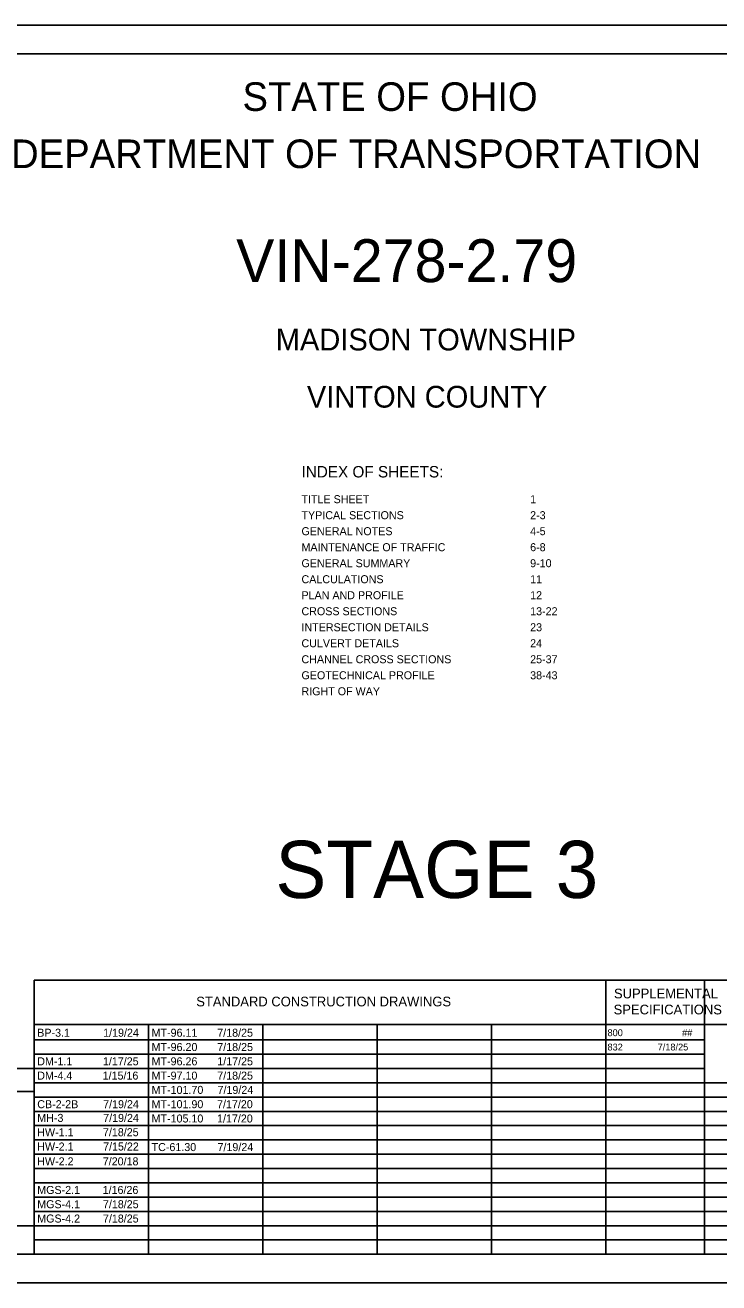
# Model space of a CAD drawing. Extents: x 0 to 34, y 0 to 22.
# Drawn here: x 9.99 to 22.13, y 0 to 22 of the extents above; entities that cross this region are included whole.
import ezdxf

# ---------------------------------------------------------------- set-up
doc = ezdxf.new("R2010")
doc.units = 0
for name, color, linetype in [('SH_Border', 7, 'Continuous'), ('SH_Cut_Line', 7, 'Continuous'), ('SH_Data', 7, 'Continuous'), ('SH_Text', 7, 'Continuous')]:
    doc.layers.add(name, color=color, linetype=linetype)

msp = doc.modelspace()

# ---------------------------------------------------------------- linework, layer by layer
at = {"layer": 'SH_Border'}
msp.add_lwpolyline([(1.5, 21.5), (33.5, 21.5), (33.5, 0.5), (1.5, 0.5)], close=True, dxfattribs=at)
at = {"layer": 'SH_Cut_Line'}
msp.add_lwpolyline([(0, 0), (34, 0), (34, 22), (0, 22)], close=True, dxfattribs=at)
at = {"layer": 'SH_Data'}
for p, q in [((10.15, 5.292), (23.6, 5.292)), ((10.15, 0.5), (10.15, 5.292)), ((20.15, 0.5), (20.15, 5.292)), ((21.875, 0.5), (21.875, 5.292)), ((10.15, 4.521), (23.6, 4.521)), ((12.15, 0.5), (12.15, 4.521)), ((14.15, 0.5), (14.15, 4.521)), ((16.15, 0.5), (16.15, 4.521)), ((18.15, 0.5), (18.15, 4.521)), ((10.15, 4.25), (21.875, 4.25)), ((10.15, 4), (21.875, 4)), ((10.15, 3.75), (7.35, 3.75)), ((10.15, 0.5), (10.15, 3.75)), ((10.15, 3.75), (21.875, 3.75)), ((10.15, 3.35), (7.35, 3.35)), ((10.15, 3.5), (23.6, 3.5)), ((10.15, 3.25), (23.6, 3.25)), ((10.15, 3), (23.6, 3)), ((10.15, 2.75), (23.6, 2.75)), ((10.15, 2.5), (23.6, 2.5)), ((10.15, 2.25), (23.6, 2.25)), ((10.15, 2), (23.6, 2)), ((10.15, 1.75), (23.6, 1.75)), ((10.15, 1.5), (23.6, 1.5)), ((10.15, 1.25), (23.6, 1.25)), ((10.15, 1), (23.6, 1)), ((10.15, 0.75), (23.6, 0.75)), ((10.15, 0.5), (7.35, 0.5))]:
    msp.add_line(p, q, dxfattribs=at)
msp.add_lwpolyline([(10.15, 0.5), (10.15, 1), (7.35, 1), (7.35, 0.5)], close=True, dxfattribs=at)

# ---------------------------------------------------------------- texts
at = {"layer": 'SH_Text'}
for s, height, p in [('STATE OF OHIO', 0.5, (13.795, 20.5)), ('DEPARTMENT OF TRANSPORTATION', 0.5, (9.747, 19.5)), ('VIN-278-2.79', 0.75, (13.684, 17.505)), ('MADISON TOWNSHIP', 0.38, (14.377, 16.31)), ('VINTON COUNTY', 0.38, (14.922, 15.31)), ('INDEX OF SHEETS:', 0.2, (14.827, 14.088)), ('TITLE SHEET', 0.14, (14.827, 13.638)), ('1', 0.14, (18.827, 13.638)), ('TYPICAL SECTIONS', 0.14, (14.827, 13.358)), ('2-3', 0.14, (18.827, 13.358)), ('GENERAL NOTES', 0.14, (14.827, 13.078)), ('4-5', 0.14, (18.827, 13.078)), ('MAINTENANCE OF TRAFFIC', 0.14, (14.827, 12.798)), ('6-8', 0.14, (18.827, 12.798)), ('GENERAL SUMMARY ', 0.14, (14.827, 12.518)), ('9-10', 0.14, (18.827, 12.518)), ('CALCULATIONS', 0.14, (14.827, 12.238)), ('11', 0.14, (18.827, 12.238)), ('PLAN AND PROFILE', 0.14, (14.827, 11.958)), ('12', 0.14, (18.827, 11.958)), ('CROSS SECTIONS', 0.14, (14.827, 11.678)), ('13-22', 0.14, (18.827, 11.678)), ('INTERSECTION DETAILS', 0.14, (14.827, 11.398)), ('23', 0.14, (18.827, 11.398)), ('CULVERT DETAILS', 0.14, (14.827, 11.118)), ('24', 0.14, (18.827, 11.118)), ('CHANNEL CROSS SECTIONS', 0.14, (14.827, 10.838)), ('25-37', 0.14, (18.827, 10.838)), ('GEOTECHNICAL PROFILE', 0.14, (14.827, 10.558)), ('38-43', 0.14, (18.827, 10.558)), ('RIGHT OF WAY', 0.14, (14.827, 10.278)), ('STAGE 3', 1, (14.37, 6.732)), ('SUPPLEMENTAL', 0.17, (20.293, 4.976)), ('STANDARD CONSTRUCTION DRAWINGS', 0.17, (12.986, 4.836)), ('SPECIFICATIONS', 0.17, (20.287, 4.696)), ('BP-3.1', 0.14, (10.205, 4.305)), ('1/19/24', 0.14, (11.358, 4.305)), ('MT-96.11', 0.14, (12.205, 4.305)), ('7/18/25', 0.14, (13.354, 4.305)), ('800', 0.12, (20.18, 4.315)), ('##', 0.12, (21.485, 4.315)), ('MT-96.20', 0.14, (12.205, 4.055)), ('7/18/25', 0.14, (13.354, 4.055)), ('832', 0.12, (20.18, 4.065)), ('7/18/25', 0.12, (21.057, 4.065)), ('DM-1.1', 0.14, (10.205, 3.805)), ('1/17/25', 0.14, (11.354, 3.805)), ('MT-96.26', 0.14, (12.205, 3.805)), ('1/17/25', 0.14, (13.354, 3.805)), ('DM-4.4', 0.14, (10.205, 3.555)), ('1/15/16', 0.14, (11.349, 3.555)), ('MT-97.10', 0.14, (12.205, 3.555)), ('7/18/25', 0.14, (13.354, 3.555)), ('MT-101.70', 0.14, (12.205, 3.305)), ('7/19/24', 0.14, (13.358, 3.305)), ('CB-2-2B', 0.14, (10.205, 3.055)), ('7/19/24', 0.14, (11.358, 3.055)), ('MT-101.90', 0.14, (12.205, 3.055)), ('7/17/20', 0.14, (13.35, 3.055)), ('MH-3', 0.14, (10.205, 2.815)), ('7/19/24', 0.14, (11.358, 2.815)), ('MT-105.10', 0.14, (12.205, 2.805)), ('1/17/20', 0.14, (13.35, 2.805)), ('HW-1.1', 0.14, (10.205, 2.565)), ('7/18/25', 0.14, (11.354, 2.565)), ('HW-2.1', 0.14, (10.205, 2.315)), ('7/15/22', 0.14, (11.357, 2.315)), ('TC-61.30', 0.14, (12.205, 2.305)), ('7/19/24', 0.14, (13.358, 2.305)), ('7/20/18', 0.14, (11.351, 2.055)), ('HW-2.2', 0.14, (10.205, 2.055)), ('MGS-2.1', 0.14, (10.205, 1.555)), ('1/16/26', 0.14, (11.349, 1.555)), ('MGS-4.1', 0.14, (10.205, 1.305)), ('7/18/25', 0.14, (11.354, 1.305)), ('MGS-4.2', 0.14, (10.205, 1.055)), ('7/18/25', 0.14, (11.354, 1.055))]:
    msp.add_text(s, height=height, dxfattribs=at).set_placement(p)

doc.saveas('drawing.dxf')
